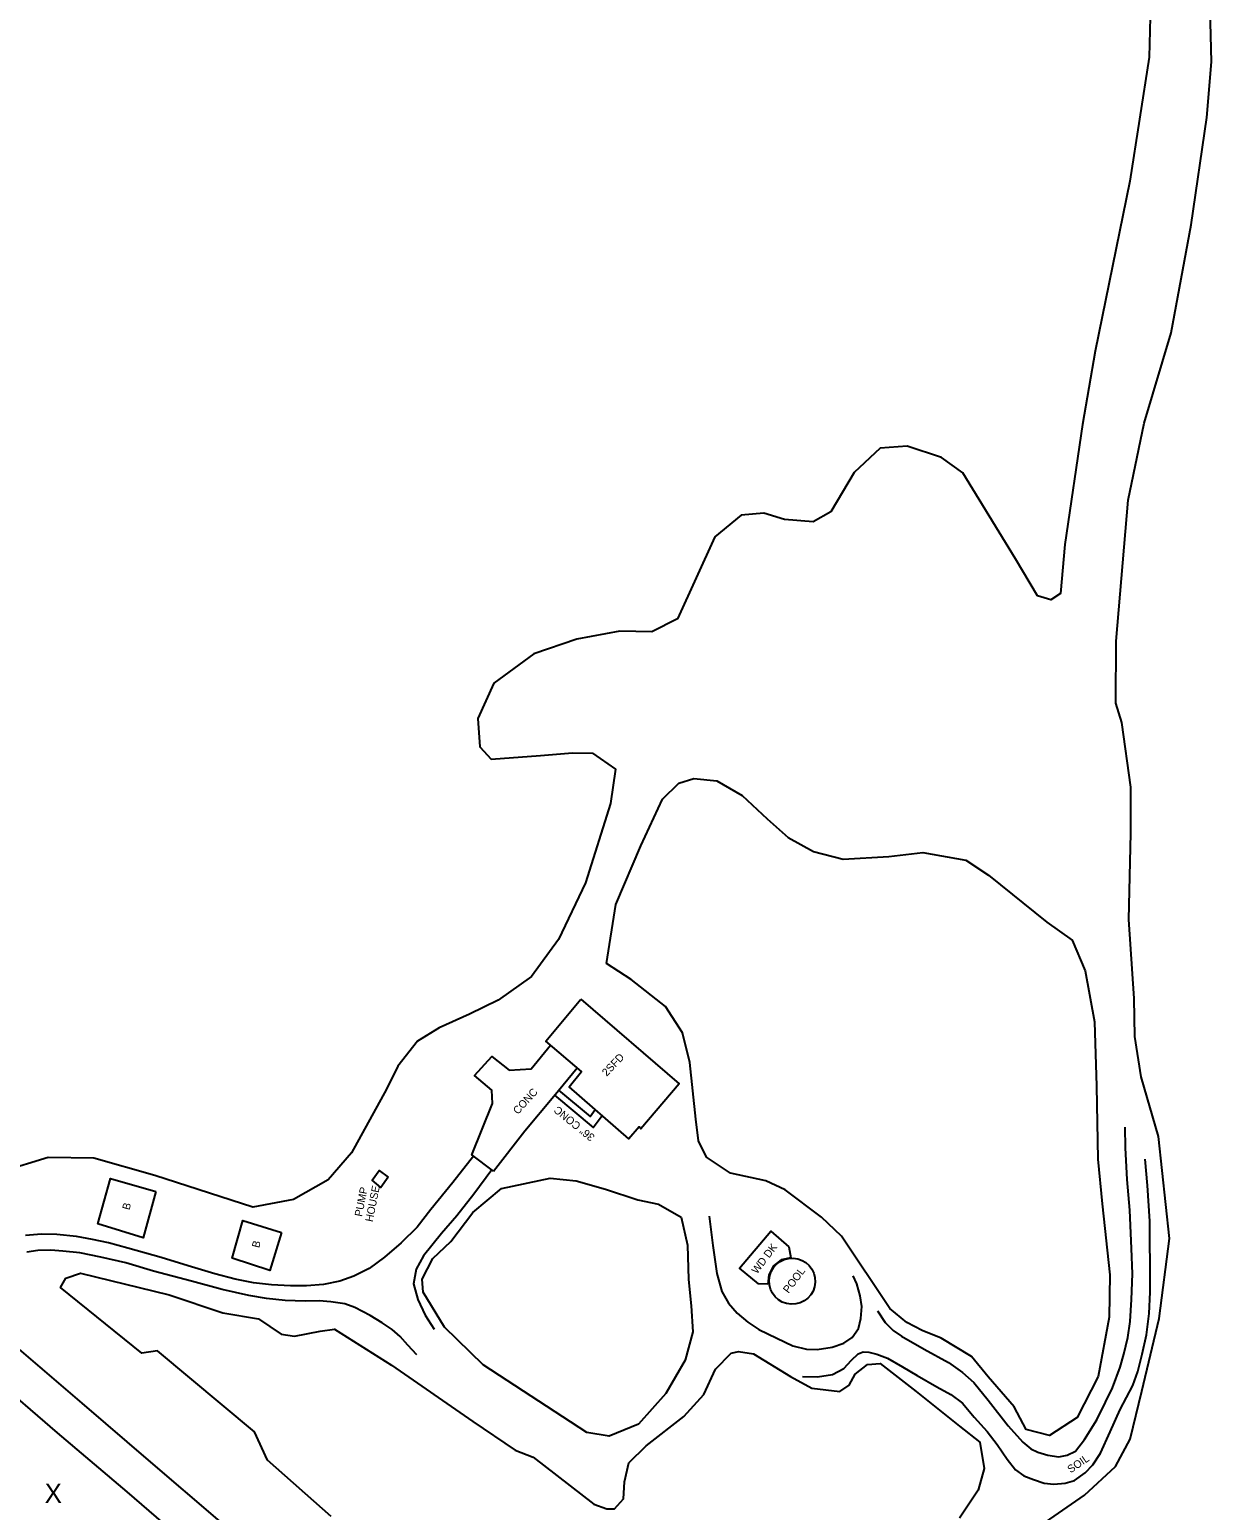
# Model space of a CAD drawing. Extents: x 2030130 to 2036320, y 723205 to 762423.
# Drawn here: x 2033381 to 2033995, y 734303 to 735072 of the extents above; entities that cross this region are included whole.
import ezdxf

# ---------------------------------------------------------------- set-up
doc = ezdxf.new("R2010")
doc.units = 0
for name, color, linetype in [('Draft_Station Labels Major', 7, 'Continuous'), ('Draft_Station Tics Major', 7, 'Continuous'), ('Exist Terrain Model Ground Surface', 7, 'Continuous'), ('Old_Level_23', 7, 'Continuous'), ('Old_Level_28', 7, 'Continuous'), ('Prop Alignment Horizontal', 7, 'Continuous'), ('Prop Alignment Vertical', 7, 'Continuous')]:
    doc.layers.add(name, color=color, linetype=linetype)

msp = doc.modelspace()

# ---------------------------------------------------------------- linework, layer by layer
at = {"layer": 'Draft_Station Labels Major'}
for points in [[(2033621.7, 734479.5), (2033610.4, 734487.99), (2033621.24, 734514.58), (2033620.86, 734521.57), (2033611.81, 734529.1), (2033620.82, 734538.95), (2033629.8, 734531.99), (2033641.29, 734532.66), (2033651.36, 734544.97)], [(2033621.7, 734479.5), (2033638.04, 734500.41), (2033653.12, 734518.51), (2033665.12, 734533.21)], [(2033821.11, 734406.99), (2033825.06, 734400.9), (2033829.37, 734396.71), (2033833.55, 734393.77), (2033845.4, 734387.07), (2033858.1, 734380.05), (2033865.34, 734374.87), (2033871.24, 734369.76), (2033878.6, 734360.48), (2033889.03, 734347.15), (2033896.61, 734338.81), (2033900.86, 734335.29), (2033904.42, 734333.61), (2033909.7, 734331.96), (2033915.4, 734331.06), (2033919.64, 734331.93), (2033924.03, 734334.14), (2033928.67, 734340.06), (2033935.11, 734350.4), (2033939.59, 734359.48), (2033943.25, 734366.97), (2033947.13, 734377.6), (2033949.13, 734384.49), (2033951.21, 734393.1), (2033952.41, 734401.46), (2033953.08, 734412.89), (2033953.63, 734426.24), (2033953.12, 734439.35), (2033952.22, 734459.16), (2033950.78, 734475.08), (2033950.03, 734491.54), (2033949.8, 734502.25)], [(2033611.36, 734487.27), (2033600.54, 734473.59), (2033589.26, 734459.54), (2033582, 734450.39), (2033573.83, 734442.32), (2033565.12, 734434.84), (2033557.13, 734428.87), (2033549.14, 734425), (2033541.87, 734422.43), (2033533.39, 734420.68), (2033524.67, 734419.99), (2033516.26, 734419.86), (2033506.35, 734420.37), (2033497.13, 734421.51), (2033487.56, 734423.44), (2033476.97, 734426.17), (2033463.2, 734430.27), (2033449.14, 734434.58), (2033431.86, 734439.4), (2033421.76, 734442.21), (2033413.42, 734443.99), (2033405.08, 734445.48), (2033394.9, 734446.57), (2033386.98, 734446.8), (2033378.64, 734446.1)], [(2033782.15, 734372.78), (2033789.98, 734372.64), (2033797.76, 734373.85), (2033803.72, 734376.95), (2033807.72, 734381.27), (2033811.2, 734384.66), (2033813.73, 734385.61), (2033816.68, 734385.49), (2033820.75, 734384.46), (2033826.29, 734382.32), (2033834.13, 734377.79), (2033841.78, 734373.27), (2033852.04, 734367.4), (2033859.23, 734363.47), (2033865.26, 734359.02), (2033871.45, 734351.79), (2033878.12, 734344.26), (2033883.37, 734337.45), (2033888.42, 734329.98), (2033892.77, 734324.35), (2033897.22, 734321.21), (2033902.21, 734319.28), (2033907.77, 734317.52), (2033912.71, 734316.84), (2033918.56, 734317.36), (2033923.49, 734318.88), (2033929, 734322.76), (2033933, 734326.99), (2033936.97, 734333.03), (2033942.02, 734344.1), (2033947.27, 734355.63), (2033953.71, 734368.16), (2033956.4, 734375.5), (2033958.59, 734384.48), (2033960.81, 734394.42), (2033962.33, 734405.63), (2033962.69, 734416.7), (2033962.8, 734430.74), (2033962.54, 734442.97), (2033962.59, 734453.57), (2033961.35, 734472.06), (2033960.2, 734485.67)], [(2033620.86, 734480.14), (2033611.55, 734467.53), (2033602.67, 734456.24), (2033594.75, 734447.11)], [(2033733.73, 734456.17), (2033735.68, 734440.9), (2033737.75, 734426.29), (2033740.23, 734416.93), (2033743.8, 734410.95), (2033748.27, 734405.8), (2033753.8, 734400.98), (2033759.57, 734397.31), (2033768.84, 734392.82), (2033777.18, 734388.84), (2033784.36, 734387.01), (2033789.8, 734386.79), (2033797.58, 734388), (2033803.69, 734390.13), (2033808.02, 734393.1), (2033811.36, 734397.74), (2033812.44, 734402.95), (2033812.98, 734409.23), (2033812.16, 734414.81), (2033810.51, 734420.99), (2033808.58, 734425.08)], [(2033594.75, 734447.11), (2033585.29, 734435.52), (2033581.61, 734428.66), (2033580.18, 734421.04), (2033582.42, 734412.75), (2033586.26, 734404.64), (2033590.93, 734397.38)], [(2033581.96, 734384.11), (2033577.29, 734389.08), (2033573.27, 734393.54), (2033569.13, 734397.25), (2033563.92, 734400.71), (2033557.58, 734404.51), (2033549.73, 734408.65), (2033544.46, 734410.49), (2033537.24, 734411.56), (2033531.25, 734412.09), (2033523.98, 734411.92), (2033513.58, 734412.35), (2033503.79, 734413.32), (2033494.59, 734414.95), (2033480.77, 734418), (2033464.8, 734422.29), (2033445.06, 734427.6), (2033430.71, 734431.82), (2033417.75, 734434.84), (2033406.95, 734437.01), (2033398.1, 734437.95), (2033391.73, 734438.5), (2033385.03, 734438.2), (2033379.36, 734437.39)], [(2033650.79, 734146.66), (2033617.2, 734178), (2033582.2, 734209.27), (2033547.47, 734239.33), (2033513.42, 734268.75), (2033478.55, 734298.65), (2033443.75, 734328.41), (2033408.02, 734358.96), (2033372.98, 734389.04), (2033337.5, 734419.76)], [(2033323.47, 734405.07), (2033360.4, 734373.29), (2033395.11, 734343.65), (2033431.25, 734312.99), (2033465.65, 734283.39), (2033500.39, 734253.62), (2033534.59, 734223.99), (2033568.5, 734194.34), (2033602.82, 734163.7), (2033636.33, 734131.87), (2033659.89, 734108.31), (2033683.47, 734083.08), (2033706.23, 734056.78), (2033727.14, 734030.65), (2033748.01, 734002.9), (2033774.83, 733965.52)]]:
    msp.add_lwpolyline(points, dxfattribs=at)
at = {"layer": 'Draft_Station Tics Major'}
for points in [[(2033994.57, 735055.68), (2033993.2, 735110.51)], [(2033963.21, 735099.8), (2033962.21, 735058.04)], [(2033962.21, 735058.04), (2033952.21, 734993.61), (2033934.28, 734905.39), (2033927.69, 734867.26), (2033918.54, 734804.92), (2033916.14, 734779.54), (2033911.18, 734776.28), (2033904.32, 734778.3), (2033892.89, 734797.54)], [(2033945.01, 734722.51), (2033945.19, 734754.73), (2033951.31, 734828.01), (2033959.72, 734867.99), (2033973.63, 734914.89), (2033984.05, 734971.01), (2033992.15, 735026.64), (2033994.57, 735055.68)], [(2033892.89, 734797.54), (2033865.52, 734842.18), (2033854.47, 734850.03), (2033836.52, 734856.08), (2033822.63, 734854.95), (2033809.02, 734842.24), (2033796.99, 734821.88), (2033787.68, 734816.77), (2033772.94, 734817.95), (2033762.08, 734821.24), (2033750.28, 734820.21), (2033736.73, 734808.83), (2033717.34, 734766.4), (2033703.97, 734759.56), (2033687.3, 734759.87), (2033664.94, 734755.68), (2033642.63, 734748.07), (2033621.91, 734733), (2033613.57, 734714.57), (2033614.67, 734699.93), (2033620.46, 734693.43), (2033646.14, 734695.4), (2033662.7, 734696.8), (2033673.11, 734696.56), (2033685.1, 734688.29), (2033682.46, 734670.39), (2033669.57, 734629.21), (2033655.46, 734599.83), (2033641.39, 734580.51), (2033624.2, 734568.33), (2033609.29, 734560.98), (2033593.45, 734553.86), (2033582.17, 734546.93), (2033571.97, 734534.08), (2033566.16, 734522), (2033547.92, 734489.01), (2033535.77, 734474.91), (2033517.91, 734464.84), (2033496.7, 734460.79), (2033445.81, 734477.31), (2033414.13, 734486.2), (2033390.45, 734486.61), (2033366.63, 734479.26)], [(2033802.71, 734240.7), (2033850.53, 734273.8), (2033865.19, 734284.38), (2033874.38, 734286.65), (2033884.24, 734286.62), (2033895.13, 734288.64), (2033908.38, 734297.19), (2033928.68, 734311.14), (2033944.84, 734326.02), (2033952.45, 734340.3), (2033958.41, 734365.27), (2033967.37, 734403.01), (2033972.87, 734444.5), (2033967.1, 734497.44), (2033958.15, 734528.53), (2033954.84, 734549.33), (2033954.52, 734569.07), (2033951.67, 734610.14), (2033952.77, 734655.03), (2033952.81, 734678.92), (2033948.13, 734712.48), (2033945.01, 734722.51)], [(2033680.35, 734587.24), (2033685.22, 734617.94), (2033698.24, 734648.5), (2033709.48, 734672.68), (2033717.98, 734681.05), (2033725.85, 734683.38), (2033737.74, 734682.13), (2033750.89, 734674.57), (2033763.85, 734662.47), (2033774.82, 734652.72), (2033787.99, 734645.54), (2033803.37, 734641.49), (2033827.13, 734642.97), (2033844.65, 734644.9), (2033867.05, 734640.94), (2033878.87, 734633.25), (2033909.14, 734608.86), (2033922.22, 734599.41), (2033928.95, 734583.59), (2033933.92, 734557.03), (2033934.82, 734523.62), (2033935.52, 734485.67), (2033937.78, 734462.44), (2033941.76, 734425.69), (2033941.42, 734403.7), (2033935.78, 734372.84), (2033924.85, 734351.49), (2033910.43, 734342.23), (2033898.43, 734345.38), (2033892.2, 734357.12), (2033878.71, 734372.74), (2033870.04, 734383.15), (2033854.31, 734392.71), (2033844.43, 734396.72), (2033836.45, 734400.84), (2033827.65, 734408.22), (2033802.47, 734445.67), (2033792.07, 734455.58), (2033773.13, 734469.83), (2033763.08, 734474.41), (2033744.86, 734478.39), (2033732.31, 734486.68), (2033728.11, 734495.2), (2033726.87, 734506.44), (2033723.73, 734535.96), (2033719.81, 734551.29), (2033711.09, 734564.92), (2033693.27, 734578.93), (2033680.35, 734587.24)], [(2033625.83, 734470.42), (2033651.09, 734475.83), (2033664.68, 734474.5), (2033679.86, 734470.08), (2033696.7, 734464.65), (2033707.41, 734462.31), (2033719.26, 734455.56), (2033722.45, 734441.02), (2033723.04, 734423.17), (2033724.37, 734409.46), (2033725.33, 734395.96), (2033721.31, 734381.34), (2033711.3, 734363.93), (2033696.99, 734348.03), (2033681.75, 734341.83), (2033670.27, 734343.83), (2033616.36, 734378.86), (2033596.29, 734398.41), (2033585.14, 734416.65), (2033584.66, 734423.31), (2033590.27, 734434.08), (2033599.55, 734442.98), (2033610.91, 734457.96), (2033625.83, 734470.42)], [(2033537.45, 734300.21), (2033504.34, 734329.46), (2033497.56, 734344.15), (2033447.16, 734386.24), (2033439.14, 734384.87), (2033396.75, 734419.04), (2033399.61, 734423.85), (2033407.3, 734426.57), (2033453.28, 734415.19), (2033481.15, 734405.88), (2033499.61, 734402.84), (2033511.41, 734394.77), (2033518.38, 734393.72), (2033531.76, 734396.39), (2033539.2, 734397.41), (2033568.76, 734378.74), (2033610.97, 734349.5), (2033632.92, 734334.56), (2033642.25, 734330.95), (2033673.85, 734306.52), (2033680.57, 734304.15), (2033684.56, 734304.18), (2033689.32, 734309.29), (2033689.69, 734318.18), (2033691.99, 734327.95), (2033701.08, 734336.86), (2033720.66, 734351.98), (2033731, 734363.5), (2033737.05, 734376.71), (2033745.16, 734384.9), (2033748.99, 734385.88), (2033756.71, 734384.62), (2033775.94, 734372.82), (2033787.07, 734366.86), (2033801.6, 734365.12), (2033806.47, 734368.34), (2033809.56, 734374.09), (2033816.02, 734379.13), (2033822.49, 734379.62), (2033841.22, 734365.02), (2033863.67, 734347.03), (2033874.27, 734338.8), (2033876.54, 734325.05), (2033873.42, 734313.8), (2033863.72, 734299.23)]]:
    msp.add_lwpolyline(points, dxfattribs=at)
at = {"layer": 'Exist Terrain Model Ground Surface'}
for points in [[(2033667.08, 734568.77), (2033718.09, 734524.91), (2033698.3, 734501.47), (2033697.39, 734502.46), (2033692.06, 734496.19), (2033660.99, 734523.27), (2033667.34, 734531.31), (2033648.89, 734547.07)], [(2033567.1, 734476.38), (2033563.25, 734471), (2033558.63, 734474.82), (2033562.27, 734479.83)], [(2033446.43, 734468.96), (2033439.8, 734444.87), (2033416.22, 734452.15), (2033422.83, 734475.67)], [(2033511.56, 734447.63), (2033505.49, 734427.92), (2033485.98, 734434.36), (2033491.56, 734453.81)]]:
    msp.add_lwpolyline(points, close=True, dxfattribs=at)
for points in [[(2033653.43, 734518.88), (2033673.46, 734502.1), (2033678.09, 734508.37)], [(2033655.53, 734521.47), (2033671.98, 734507.89), (2033674.51, 734511.48)], [(2033764.22, 734420.8), (2033759.35, 734421), (2033749.56, 734429.14), (2033765.83, 734448.24), (2033775.14, 734440.12), (2033776.15, 734434.53), (2033771.14, 734433.4), (2033767.09, 734430.23), (2033764.7, 734425.65), (2033764.22, 734420.8)]]:
    msp.add_lwpolyline(points, dxfattribs=at)
at = {"layer": 'Prop Alignment Horizontal'}
msp.add_ellipse((2033776.83, 734422.33), major_axis=(-11.98, 0.5), ratio=0.999201, dxfattribs=at)

# ---------------------------------------------------------------- texts
at = {"layer": 'Draft_Station Tics Major'}
msp.add_text('X', height=10, dxfattribs=at).set_placement((2033388.63, 734307.2))
at = {"layer": 'Old_Level_23'}
for s, rotation, p in [('CONC', 47.83744, (2033634.4, 734508.65)), ('SOIL', 34.25217, (2033921.5, 734322.51))]:
    msp.add_text(s, height=4, rotation=rotation, dxfattribs=at).set_placement(p)
at = {"layer": 'Old_Level_28'}
for s, rotation, p in [('2SFD', 46.20701, (2033680.5, 734528.47)), ('36" CONC', 140.86775, (2033674.65, 734497.76)), ('PUMP', 78.71343, (2033553.41, 734455.63)), ('HOUSE', 78.71343, (2033558.98, 734452.9)), ('B', 75.00003, (2033432.64, 734459.03)), ('B', 75.56739, (2033499.98, 734439.35)), ('WD DK', 52.90845, (2033758.59, 734425.78))]:
    msp.add_text(s, height=4, rotation=rotation, dxfattribs=at).set_placement(p)
at = {"layer": 'Prop Alignment Vertical'}
msp.add_text('POOL', height=4, rotation=53.18767, dxfattribs=at).set_placement((2033774.93, 734415.74))

doc.saveas('drawing.dxf')
